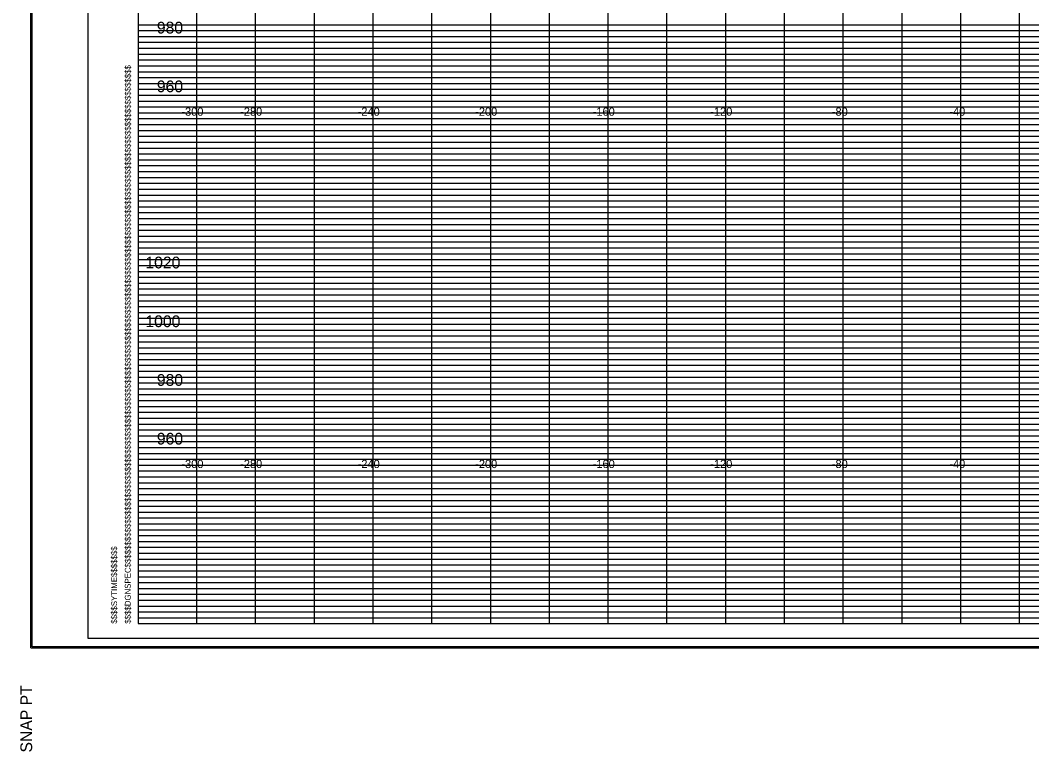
# Model space of a CAD drawing. Extents: x 2313580 to 2322968, y 282099 to 303247.
# Drawn here: x 2316050 to 2316394.2, y 287544 to 287793.2 of the extents above; entities that cross this region are included whole.
import ezdxf

# ---------------------------------------------------------------- set-up
doc = ezdxf.new("R2010")
doc.units = 0
for name, color, linetype in [('DESIGN - SHEET - Corner Text', 7, 'Continuous'), ('DESIGN - SHEET - Light Grid', 7, 'Continuous'), ('DESIGN - SHEET - Linework', 7, 'Continuous'), ('DESIGN - SHEET - Plot Shape', 7, 'Continuous'), ('DESIGN - TYPICAL - Text', 7, 'Continuous')]:
    doc.layers.add(name, color=color, linetype=linetype)

msp = doc.modelspace()

# ---------------------------------------------------------------- linework, layer by layer
at = {"layer": 'DESIGN - SHEET - Light Grid'}
for p, q in [((2316090.08, 287791.67), (2316250.08, 287791.67)), ((2316250.08, 287791.67), (2316410.08, 287791.67)), ((2316090.08, 287789.67), (2316250.08, 287789.67)), ((2316250.08, 287789.67), (2316410.08, 287789.67)), ((2316090.08, 287785.67), (2316250.08, 287785.67)), ((2316250.08, 287785.67), (2316410.08, 287785.67)), ((2316090.08, 287783.67), (2316250.08, 287783.67)), ((2316090.08, 287781.67), (2316250.08, 287781.67)), ((2316250.08, 287783.67), (2316410.08, 287783.67)), ((2316250.08, 287781.67), (2316410.08, 287781.67)), ((2316090.08, 287779.67), (2316250.08, 287779.67)), ((2316090.08, 287777.67), (2316250.08, 287777.67)), ((2316250.08, 287779.67), (2316410.08, 287779.67)), ((2316250.08, 287777.67), (2316410.08, 287777.67)), ((2316090.08, 287775.67), (2316250.08, 287775.67)), ((2316090.08, 287773.67), (2316250.08, 287773.67)), ((2316250.08, 287775.67), (2316410.08, 287775.67)), ((2316250.08, 287773.67), (2316410.08, 287773.67)), ((2316090.08, 287771.67), (2316250.08, 287771.67)), ((2316250.08, 287771.67), (2316410.08, 287771.67)), ((2316090.08, 287769.67), (2316250.08, 287769.67)), ((2316250.08, 287769.67), (2316410.08, 287769.67)), ((2316090.08, 287765.67), (2316250.08, 287765.67)), ((2316090.08, 287763.67), (2316250.08, 287763.67)), ((2316250.08, 287765.67), (2316410.08, 287765.67)), ((2316250.08, 287763.67), (2316410.08, 287763.67)), ((2316090.08, 287761.67), (2316250.08, 287761.67)), ((2316250.08, 287761.67), (2316410.08, 287761.67)), ((2316090.08, 287759.67), (2316250.08, 287759.67)), ((2316090.08, 287757.67), (2316250.08, 287757.67)), ((2316250.08, 287759.67), (2316410.08, 287759.67)), ((2316250.08, 287757.67), (2316410.08, 287757.67)), ((2316090.08, 287755.67), (2316250.08, 287755.67)), ((2316090.08, 287753.67), (2316250.08, 287753.67)), ((2316250.08, 287755.67), (2316410.08, 287755.67)), ((2316250.08, 287753.67), (2316410.08, 287753.67)), ((2316090.08, 287751.67), (2316250.08, 287751.67)), ((2316090.08, 287749.67), (2316250.08, 287749.67)), ((2316250.08, 287751.67), (2316410.08, 287751.67)), ((2316250.08, 287749.67), (2316410.08, 287749.67)), ((2316090.08, 287745.67), (2316250.08, 287745.67)), ((2316090.08, 287743.67), (2316250.08, 287743.67)), ((2316250.08, 287745.67), (2316410.08, 287745.67)), ((2316250.08, 287743.67), (2316410.08, 287743.67)), ((2316090.08, 287741.67), (2316250.08, 287741.67)), ((2316090.08, 287739.67), (2316250.08, 287739.67)), ((2316250.08, 287741.67), (2316410.08, 287741.67)), ((2316250.08, 287739.67), (2316410.08, 287739.67)), ((2316090.08, 287737.67), (2316250.08, 287737.67)), ((2316090.08, 287735.67), (2316250.08, 287735.67)), ((2316250.08, 287737.67), (2316410.08, 287737.67)), ((2316250.08, 287735.67), (2316410.08, 287735.67)), ((2316090.08, 287733.67), (2316250.08, 287733.67)), ((2316250.08, 287733.67), (2316410.08, 287733.67)), ((2316090.08, 287731.67), (2316250.08, 287731.67)), ((2316090.08, 287729.67), (2316250.08, 287729.67)), ((2316250.08, 287731.67), (2316410.08, 287731.67)), ((2316250.08, 287729.67), (2316410.08, 287729.67)), ((2316090.08, 287725.67), (2316250.08, 287725.67)), ((2316250.08, 287725.67), (2316410.08, 287725.67)), ((2316090.08, 287723.67), (2316250.08, 287723.67)), ((2316250.08, 287723.67), (2316410.08, 287723.67)), ((2316090.08, 287721.67), (2316250.08, 287721.67)), ((2316090.08, 287719.67), (2316250.08, 287719.67)), ((2316250.08, 287721.67), (2316410.08, 287721.67)), ((2316250.08, 287719.67), (2316410.08, 287719.67)), ((2316090.08, 287717.67), (2316250.08, 287717.67)), ((2316090.08, 287715.67), (2316250.08, 287715.67)), ((2316250.08, 287717.67), (2316410.08, 287717.67)), ((2316250.08, 287715.67), (2316410.08, 287715.67)), ((2316090.08, 287713.67), (2316250.08, 287713.67)), ((2316090.08, 287711.67), (2316250.08, 287711.67)), ((2316250.08, 287713.67), (2316410.08, 287713.67)), ((2316250.08, 287711.67), (2316410.08, 287711.67)), ((2316090.08, 287709.67), (2316250.08, 287709.67)), ((2316250.08, 287709.67), (2316410.08, 287709.67)), ((2316090.08, 287705.67), (2316250.08, 287705.67)), ((2316250.08, 287705.67), (2316410.08, 287705.67)), ((2316090.08, 287703.67), (2316250.08, 287703.67)), ((2316090.08, 287701.67), (2316250.08, 287701.67)), ((2316250.08, 287703.67), (2316410.08, 287703.67)), ((2316250.08, 287701.67), (2316410.08, 287701.67)), ((2316090.08, 287699.67), (2316250.08, 287699.67)), ((2316250.08, 287699.67), (2316410.08, 287699.67)), ((2316090.08, 287697.67), (2316250.08, 287697.67)), ((2316090.08, 287695.67), (2316250.08, 287695.67)), ((2316250.08, 287697.67), (2316410.08, 287697.67)), ((2316250.08, 287695.67), (2316410.08, 287695.67)), ((2316090.08, 287693.67), (2316250.08, 287693.67)), ((2316090.08, 287691.67), (2316250.08, 287691.67)), ((2316250.08, 287693.67), (2316410.08, 287693.67)), ((2316250.08, 287691.67), (2316410.08, 287691.67)), ((2316090.08, 287689.67), (2316250.08, 287689.67)), ((2316250.08, 287689.67), (2316410.08, 287689.67)), ((2316090.08, 287685.67), (2316250.08, 287685.67)), ((2316250.08, 287685.67), (2316410.08, 287685.67)), ((2316090.08, 287683.67), (2316250.08, 287683.67)), ((2316090.08, 287681.67), (2316250.08, 287681.67)), ((2316250.08, 287683.67), (2316410.08, 287683.67)), ((2316250.08, 287681.67), (2316410.08, 287681.67)), ((2316090.08, 287679.67), (2316250.08, 287679.67)), ((2316090.08, 287677.67), (2316250.08, 287677.67)), ((2316250.08, 287679.67), (2316410.08, 287679.67)), ((2316250.08, 287677.67), (2316410.08, 287677.67)), ((2316090.08, 287675.67), (2316250.08, 287675.67)), ((2316090.08, 287673.67), (2316250.08, 287673.67)), ((2316250.08, 287675.67), (2316410.08, 287675.67)), ((2316250.08, 287673.67), (2316410.08, 287673.67)), ((2316090.08, 287671.67), (2316250.08, 287671.67)), ((2316250.08, 287671.67), (2316410.08, 287671.67)), ((2316090.08, 287669.67), (2316250.08, 287669.67)), ((2316250.08, 287669.67), (2316410.08, 287669.67)), ((2316090.08, 287665.67), (2316250.08, 287665.67)), ((2316090.08, 287663.67), (2316250.08, 287663.67)), ((2316250.08, 287665.67), (2316410.08, 287665.67)), ((2316250.08, 287663.67), (2316410.08, 287663.67)), ((2316090.08, 287661.67), (2316250.08, 287661.67)), ((2316250.08, 287661.67), (2316410.08, 287661.67)), ((2316090.08, 287659.67), (2316250.08, 287659.67)), ((2316090.08, 287657.67), (2316250.08, 287657.67)), ((2316250.08, 287659.67), (2316410.08, 287659.67)), ((2316250.08, 287657.67), (2316410.08, 287657.67)), ((2316090.08, 287655.67), (2316250.08, 287655.67)), ((2316090.08, 287653.67), (2316250.08, 287653.67)), ((2316250.08, 287655.67), (2316410.08, 287655.67)), ((2316250.08, 287653.67), (2316410.08, 287653.67)), ((2316090.08, 287651.67), (2316250.08, 287651.67)), ((2316090.08, 287649.67), (2316250.08, 287649.67)), ((2316250.08, 287651.67), (2316410.08, 287651.67)), ((2316250.08, 287649.67), (2316410.08, 287649.67)), ((2316090.08, 287645.67), (2316250.08, 287645.67)), ((2316090.08, 287643.67), (2316250.08, 287643.67)), ((2316250.08, 287645.67), (2316410.08, 287645.67)), ((2316250.08, 287643.67), (2316410.08, 287643.67)), ((2316090.08, 287641.67), (2316250.08, 287641.67)), ((2316090.08, 287639.67), (2316250.08, 287639.67)), ((2316250.08, 287641.67), (2316410.08, 287641.67)), ((2316250.08, 287639.67), (2316410.08, 287639.67)), ((2316090.08, 287637.67), (2316250.08, 287637.67)), ((2316250.08, 287637.67), (2316410.08, 287637.67)), ((2316090.08, 287635.67), (2316250.08, 287635.67)), ((2316090.08, 287633.67), (2316250.08, 287633.67)), ((2316250.08, 287635.67), (2316410.08, 287635.67)), ((2316250.08, 287633.67), (2316410.08, 287633.67)), ((2316090.08, 287631.67), (2316250.08, 287631.67)), ((2316090.08, 287629.67), (2316250.08, 287629.67)), ((2316250.08, 287631.67), (2316410.08, 287631.67)), ((2316250.08, 287629.67), (2316410.08, 287629.67)), ((2316090.08, 287625.67), (2316250.08, 287625.67)), ((2316250.08, 287625.67), (2316410.08, 287625.67)), ((2316090.08, 287623.67), (2316250.08, 287623.67)), ((2316250.08, 287623.67), (2316410.08, 287623.67)), ((2316090.08, 287621.67), (2316250.08, 287621.67)), ((2316090.08, 287619.67), (2316250.08, 287619.67)), ((2316250.08, 287621.67), (2316410.08, 287621.67)), ((2316250.08, 287619.67), (2316410.08, 287619.67)), ((2316090.08, 287617.67), (2316250.08, 287617.67)), ((2316090.08, 287615.67), (2316250.08, 287615.67)), ((2316250.08, 287617.67), (2316410.08, 287617.67)), ((2316250.08, 287615.67), (2316410.08, 287615.67)), ((2316090.08, 287613.67), (2316250.08, 287613.67)), ((2316090.08, 287611.67), (2316250.08, 287611.67)), ((2316250.08, 287613.67), (2316410.08, 287613.67)), ((2316250.08, 287611.67), (2316410.08, 287611.67)), ((2316090.08, 287609.67), (2316250.08, 287609.67)), ((2316250.08, 287609.67), (2316410.08, 287609.67)), ((2316090.08, 287605.67), (2316250.08, 287605.67)), ((2316250.08, 287605.67), (2316410.08, 287605.67)), ((2316090.08, 287603.67), (2316250.08, 287603.67)), ((2316090.08, 287601.67), (2316250.08, 287601.67)), ((2316250.08, 287603.67), (2316410.08, 287603.67)), ((2316250.08, 287601.67), (2316410.08, 287601.67)), ((2316090.08, 287599.67), (2316250.08, 287599.67)), ((2316250.08, 287599.67), (2316410.08, 287599.67)), ((2316090.08, 287597.67), (2316250.08, 287597.67)), ((2316090.08, 287595.67), (2316250.08, 287595.67)), ((2316250.08, 287597.67), (2316410.08, 287597.67)), ((2316250.08, 287595.67), (2316410.08, 287595.67)), ((2316090.08, 287593.67), (2316250.08, 287593.67)), ((2316090.08, 287591.67), (2316250.08, 287591.67)), ((2316250.08, 287593.67), (2316410.08, 287593.67)), ((2316250.08, 287591.67), (2316410.08, 287591.67)), ((2316090.08, 287589.67), (2316250.08, 287589.67)), ((2316250.08, 287589.67), (2316410.08, 287589.67))]:
    msp.add_line(p, q, dxfattribs=at)
at = {"layer": 'DESIGN - SHEET - Linework'}
for p, q in [((2316053.62, 287579.39), (2316053.62, 288015.95)), ((2316110.08, 287587.67), (2316110.08, 288007.67)), ((2316130.08, 287587.67), (2316130.08, 288007.67)), ((2316150.08, 287587.67), (2316150.08, 288007.67)), ((2316170.08, 287587.67), (2316170.08, 288007.67)), ((2316190.08, 287587.67), (2316190.08, 288007.67)), ((2316210.08, 287587.67), (2316210.08, 288007.67)), ((2316230.08, 287587.67), (2316230.08, 288007.67)), ((2316250.08, 287587.67), (2316250.08, 288007.67)), ((2316270.08, 287587.67), (2316270.08, 288007.67)), ((2316290.08, 287587.67), (2316290.08, 288007.67)), ((2316310.08, 287587.67), (2316310.08, 288007.67)), ((2316330.08, 287587.67), (2316330.08, 288007.67)), ((2316350.08, 287587.67), (2316350.08, 288007.67)), ((2316370.08, 287587.67), (2316370.08, 288007.67)), ((2316390.08, 287587.67), (2316390.08, 288007.67)), ((2316090.08, 287787.67), (2316730.08, 287787.67)), ((2316090.08, 287767.67), (2316730.08, 287767.67)), ((2316090.08, 287747.67), (2316730.08, 287747.67)), ((2316090.08, 287727.67), (2316730.08, 287727.67)), ((2316090.08, 287707.67), (2316730.08, 287707.67)), ((2316090.08, 287687.67), (2316730.08, 287687.67)), ((2316090.08, 287667.67), (2316730.08, 287667.67)), ((2316090.08, 287647.67), (2316730.08, 287647.67)), ((2316090.08, 287627.67), (2316730.08, 287627.67)), ((2316090.08, 287607.67), (2316730.08, 287607.67)), ((2316053.62, 287579.39), (2316734.42, 287579.39))]:
    msp.add_line(p, q, dxfattribs=at)
msp.add_lwpolyline([(2316090.08, 288007.67), (2316090.08, 287587.67), (2316730.08, 287587.67), (2316730.08, 288007.67), (2316090.08, 288007.67)], dxfattribs=at)
at = {"layer": 'DESIGN - SHEET - Plot Shape'}
for points in [[(2316054.02, 288015.55), (2316734.02, 288015.55), (2316734.02, 287579.79), (2316054.02, 287579.79)], [(2316073.08, 288007.67), (2316730.08, 288007.67), (2316730.08, 287582.67), (2316073.08, 287582.67)]]:
    msp.add_lwpolyline(points, close=True, dxfattribs=at)

# ---------------------------------------------------------------- texts
at = {"layer": 'DESIGN - SHEET - Corner Text'}
for s, height, p in [('$$$$DGNSPEC$$$$$$$$$$$$$$$$$$$$$$$$$$$$$$$$$$$$$$$$$$$$$$$$$$$$$$$$$$$$$$$$$$$$$$$$$$$$$$$$$$$$$$$$$$$$$$$$$$$$$$$$$$$$$$$$$$$', 2.00004, (2316087.56, 287587.67)), ('$$$$SYTIME$$$$$$$', 2, (2316082.92, 287587.67)), ('SNAP PT  ', 4, (2316054.02, 287543.79))]:
    msp.add_text(s, height=height, rotation=90, dxfattribs=at).set_placement(p)
at = {"layer": 'DESIGN - SHEET - Linework'}
for p in [(2316110.08, 287767.67), (2316110.08, 287647.67)]:
    msp.add_text('-', height=0.0001, dxfattribs=at).set_placement(p)
at = {"layer": 'DESIGN - TYPICAL - Text'}
for s, height, p in [('980', 4, (2316096.46, 287788.67)), ('960', 4, (2316096.46, 287768.67)), ('-300', 2.8, (2316104.82, 287760.67)), ('-280', 2.8, (2316124.82, 287760.67)), ('-240', 2.8, (2316164.82, 287760.67)), ('-200', 2.8, (2316204.82, 287760.67)), ('-160', 2.8, (2316244.82, 287760.67)), ('-120', 2.8, (2316284.82, 287760.67)), ('-80', 2.8, (2316326.19, 287760.67)), ('-40', 2.8, (2316366.19, 287760.67)), ('1020', 4, (2316092.56, 287708.67)), ('1000', 4, (2316092.56, 287688.67)), ('980', 4, (2316096.46, 287668.67)), ('960', 4, (2316096.46, 287648.67)), ('-300', 2.8, (2316104.82, 287640.67)), ('-280', 2.8, (2316124.82, 287640.67)), ('-240', 2.8, (2316164.82, 287640.67)), ('-200', 2.8, (2316204.82, 287640.67)), ('-160', 2.8, (2316244.82, 287640.67)), ('-120', 2.8, (2316284.82, 287640.67)), ('-80', 2.8, (2316326.19, 287640.67)), ('-40', 2.8, (2316366.19, 287640.67))]:
    msp.add_text(s, height=height, dxfattribs=at).set_placement(p)

doc.saveas('drawing.dxf')
